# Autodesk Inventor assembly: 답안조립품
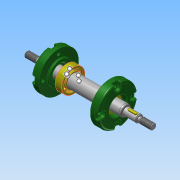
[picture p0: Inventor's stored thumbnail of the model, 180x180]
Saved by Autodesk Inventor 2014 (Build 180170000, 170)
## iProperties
Created: 2016-07
Part Number: 답안조립품
Document SubType Name: Assembly
Designer: Administrator
Author: Administrator
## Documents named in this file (8)
- C:\Users\Administrator\Desktop\460707V1006\답안조립품.iam
- C:\Users\Administrator\Desktop\460707V1006\본체.ipt
- C:\Users\Administrator\Desktop\460707V1006\축.ipt
- C:\Users\Administrator\Desktop\460707V1006\키 3 x 3 x 12.ipt
- C:\Users\Administrator\Desktop\460707V1006\스퍼기어.ipt
- C:\Users\Administrator\Desktop\460707V1006\베어링 15 x 32 x 9.ipt
- C:\Users\Administrator\Desktop\460707V1006\커버.ipt
- C:\Users\Administrator\Desktop\460707V1006\V벨트풀리.ipt
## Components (3 placed, 2 different names)
1. KS B 2023 6002 - 15 x 32 x 9:2
2. V벨트풀리:1 — 각도:4
3. KS B 2023 6002 - 15 x 32 x 9:3
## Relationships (1: Angle 1)
- 각도:4 [Angle]: V벨트풀리:1
